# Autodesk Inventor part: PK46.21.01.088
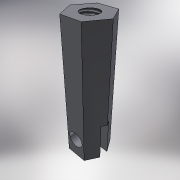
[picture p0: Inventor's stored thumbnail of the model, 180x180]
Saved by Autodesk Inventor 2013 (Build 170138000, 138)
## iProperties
Shininess: 64.0
Length Units: 11269
Angle Units: 11279
Time Units: 11290
Mass Units: 11283
Length Display Precision: 3
Angle Display Precision: 2
Compacted: True
Part Number: PK46.21.01.088
Document SubType Name: Modeling
Created: 2005-02
Material: Сталь низкоуглеродистая
Designer: PVitaliy
Manufacturer: Standard
Standards Organization: Custom
Description: Вилка
Density: 7.86 g/cm^3
Mass: 25.2754 g
Surface Area: 22.752 cm^2
Volume: 3.2157 cm^3
Density: 0.0
Volumn: 0.0
Area: 0.0
PropertySet Name: Model Information
Control State: 0
Master: False
Checked Out: False
Author: PVitaliy
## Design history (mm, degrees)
sketch "Эскиз1"
  geometry: L1 (6.351, 0)-(3.175, -5.5); L2 (3.175, -5.5)-(-3.175, -5.5); L3 (-3.175, -5.5)-(-6.351, 0); L4 (-6.351, 0)-(-3.175, 5.5); L5 (-3.175, 5.5)-(3.175, 5.5); L6 (3.175, 5.5)-(6.351, 0); 1 further point
  constraints: 12 end point, 12 other
  dimensions: "d0" = 11 distance between parallel lines of L2 L5
extrude "Выдавливание1" new body sketch "Эскиз1" distance "d1" = 40; taper "d2" = 0 deg
sketch "Эскиз2"
  geometry: L1 (-3.175, -5.5)-(3.175, -5.5) reference; L2 (3.175, 5.5)-(-3.175, 5.5) reference; L3 (-6.351, 0)-(-3.175, -5.5) reference; L4 (3.175, -5.5)-(6.351, 0) reference; L5 (6.351, 0)-(3.175, 5.5) reference; L6 (-3.175, 5.5)-(-6.351, 0) reference; L7 (-8.891, 0)-(8.891, 0) reference; L8 (-5.485, -1.5)-(5.485, -1.5); L9 (-5.485, 1.5)-(5.485, 1.5)
  constraints: 4 end point, 4 point on line, 2 parallel
  dimensions: "d7" = 3 distance between parallel lines of L9 L8; "d8" = 1.5 distance between parallel lines of L7 L8
extrude "Выдавливание2" cut sketch "Эскиз2" distance "d5" = 12; taper "d6" = 0 deg
sketch "Эскиз4"
  geometry: C1 r 2.5 at (0, 0)
  constraints: 1 centre point, 1 other
  dimensions: "d9" = 5 diameter of C1
extrude "Выдавливание3" cut sketch "Эскиз4" distance "d10" = 20; taper "d11" = 0 deg
feature "Резьба1" dims "d12" = 10, "d13" = 0
sketch "Эскиз5"
  geometry: L1 (0, 0)-(6.351, 0) reference; L2 (0, 0)-(0, -40) reference; L3 (3.175, 0)-(3.175, -6)
  constraints: 2 end point, 1 midpoint, 1 parallel
  dimensions: "d14" = 6 distance of L3.start L3.end
hole "Отверстие1" sketch "Эскиз5" diameter "d15" = 5; stored, may be unused: countersink angle "d19" = 82 deg, drill point angle "d21" = 118 deg; dims "d16" = 6, "d17" = 4, "d18" = 2, "d20" = 8
body "Solid1"
